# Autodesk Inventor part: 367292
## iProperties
Created: 2006-06
Part Number: 367292
Material: 8.8 vz
Description: Sperrzahnschraube
Document SubType Name: Modeling
Designer: I.Baliuc
Density: 7.85 g/cm^3
Abmessung: M6 x 10
Author: T.Messerschmitt
Revision Number: 367292
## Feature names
1. Basis1
